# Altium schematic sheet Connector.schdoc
size 76 x 571 mm
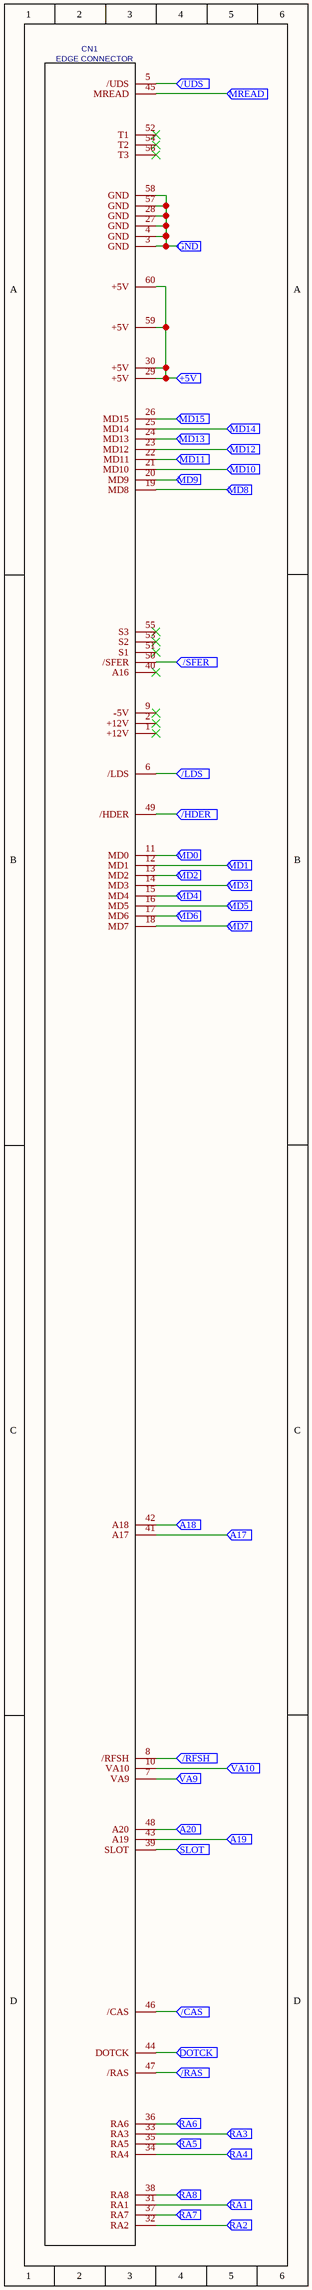
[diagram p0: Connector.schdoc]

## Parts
CN1  EDGE CONNECTOR  [LISA RAM EDGE CONNECTOR]

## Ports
+5V (in), /CAS (in), /HDER (in), /LDS (in), /RAS (in), /RFSH (in), /SFER (in), /UDS (in), A17 (in), A18 (in), A19 (in), A20 (in), DOTCK (in), GND (in), MD0 (in), MD1 (in), MD2 (in), MD3 (in), MD4 (in), MD5 (in), MD6 (in), MD7 (in), MD8 (in), MD9 (in), MD10 (in), MD11 (in), MD12 (in), MD13 (in), MD14 (in), MD15 (in), MREAD (in), RA1 (in), RA2 (in), RA3 (in), RA4 (in), RA5 (in), RA6 (in), RA7 (in), RA8 (in), SLOT (in), VA9 (in), VA10 (in)

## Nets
+5V: CN1.29(+5V) CN1.30(+5V) CN1.59(+5V) CN1.60(+5V) ; port +5V
/CAS: CN1.46(/CAS) ; port /CAS
/HDER: CN1.49(/HDER) ; port /HDER
/LDS: CN1.6(/LDS) ; port /LDS
/RAS: CN1.47(/RAS) ; port /RAS
/RFSH: CN1.8(/RFSH) ; port /RFSH
/SFER: CN1.50(/SFER) ; port /SFER
/UDS: CN1.5(/UDS) ; port /UDS
A17: CN1.41(A17) ; port A17
A18: CN1.42(A18) ; port A18
A19: CN1.43(A19) ; port A19
A20: CN1.48(A20) ; port A20
DOTCK: CN1.44(DOTCK) ; port DOTCK
GND: CN1.3(GND) CN1.4(GND) CN1.27(GND) CN1.28(GND) CN1.57(GND) CN1.58(GND) ; port GND
MD0: CN1.11(MD0) ; port MD0
MD1: CN1.12(MD1) ; port MD1
MD2: CN1.13(MD2) ; port MD2
MD3: CN1.14(MD3) ; port MD3
MD4: CN1.15(MD4) ; port MD4
MD5: CN1.16(MD5) ; port MD5
MD6: CN1.17(MD6) ; port MD6
MD7: CN1.18(MD7) ; port MD7
MD8: CN1.19(MD8) ; port MD8
MD9: CN1.20(MD9) ; port MD9
MD10: CN1.21(MD10) ; port MD10
MD11: CN1.22(MD11) ; port MD11
MD12: CN1.23(MD12) ; port MD12
MD13: CN1.24(MD13) ; port MD13
MD14: CN1.25(MD14) ; port MD14
MD15: CN1.26(MD15) ; port MD15
MREAD: CN1.45(MREAD) ; port MREAD
RA1: CN1.31(RA1) ; port RA1
RA2: CN1.32(RA2) ; port RA2
RA3: CN1.33(RA3) ; port RA3
RA4: CN1.34(RA4) ; port RA4
RA5: CN1.35(RA5) ; port RA5
RA6: CN1.36(RA6) ; port RA6
RA7: CN1.37(RA7) ; port RA7
RA8: CN1.38(RA8) ; port RA8
SLOT: CN1.39(SLOT) ; port SLOT
VA9: CN1.7(VA9) ; port VA9
VA10: CN1.10(VA10) ; port VA10

Not connected (* = marked no-connect by the designer): CN1 1(+12V)* 2(+12V)* 9(-5V)* 40(A16)* 51(S1)* 52(T1)* 53(S2)* 54(T2)* 55(S3)* 56(T3)*

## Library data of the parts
CN1 = EDGE CONNECTOR: Contributor: will_tooker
